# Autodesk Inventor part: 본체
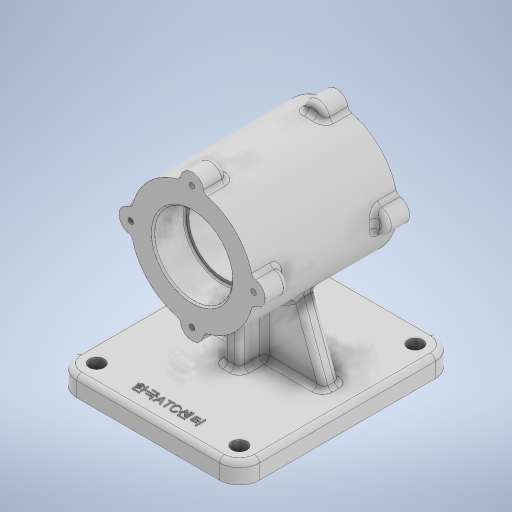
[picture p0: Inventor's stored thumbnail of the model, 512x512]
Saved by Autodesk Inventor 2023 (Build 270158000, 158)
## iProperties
Created: 2023-08
Part Number: 본체
Material: 일반
Document SubType Name: Modeling
Designer: asung
Density: 1 g/cm^3
Appearance: 기본값
Author: asung
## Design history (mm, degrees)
sketch "스케치1"
  geometry: L1 (43, 65)-(-43, 65); L2 (-55, 53)-(-55, -53); L3 (-43, -65)-(43, -65); L4 (55, -53)-(55, 53); L5 (55, 65)-(-55, -65); L6 (-55, 65)-(55, -65); C1 r 4.5 at (43, 53); C2 r 4.5 at (43, -53); C3 r 4.5 at (-43, 53); C4 r 4.5 at (-43, -53); A1 r 12 centre (-43, 53) between (-43, 65) and (-55, 53); A2 r 12 centre (-43, -53) between (-55, -53) and (-43, -65); A3 r 12 centre (43, -53) between (43, -65) and (55, -53); A4 r 12 centre (43, 53) between (55, 53) and (43, 65); 1 further point
  constraints: 12 end point, 8 centre point, 8 point on circle, 8 point on line, 8 tangent, 4 coincident, 3 equal radius, 2 midpoint, 2 parallel, 1 horizontal, 1 perpendicular
  dimensions: "d0" = 110 distance of L6.end L5.end; "d1" = 130 distance of L5.end L6.start; "d2" = 12 radius of A1; "d3" = 9 diameter of C1; "d4" = 9 diameter of C2; "d5" = 9 diameter of C3; "d6" = 9 diameter of C4
extrude "돌출1" new body sketch "스케치1" distance "d7" = 12; taper "d8" = 0 deg
fillet "모깎기1" dims "d9" = 3
sketch "스케치2"
  geometry: L1 (12, 62)-(12, -62) reference; L2 (9, -65)-(0, -65) reference; L3 (0, -65)-(0, 65) reference; L4 (0, 65)-(9, 65) reference; L5 (0, 53)-(0, 65) reference; L6 (0, 65)-(0, -5); L7 (0, -53)-(0, 53) reference; L8 (0, 65)-(0, -5); L9 (0, -5)-(82, -5); L10 (82, 38.5)-(82, -48.5); L11 (82, 38.5)-(119, 38.5); L12 (119, 38.5)-(119, -48.5); L13 (119, -48.5)-(82, -48.5); A1 r 3 centre (9, 62) between (12, 62) and (9, 65) reference; A2 r 3 centre (9, -62) between (9, -65) and (12, -62) reference; 1 further point
  constraints: 14 end point, 2 perpendicular, 2 vertical, 1 horizontal, 1 midpoint, 1 point on line
  dimensions: "d12" = 70 distance of L3.end L6.end; "d13" = 82 distance of L9.end L6.end; "d14" = 87 distance of L10.start L10.end; "d15" = 37 distance of L10.start L11.end; "d16" = 87 distance of L11.end L12.end
  node "절단 모서리 투영1"
sketch "스케치3"
  geometry: 1 further point
sketch "스케치4"
  geometry: 1 further point
revolve "회전1" stored, may be unused: angle "d17" = 90 deg
sketch "스케치5"
  geometry: C1 r 37 at (0, 0) reference; 2 further points
  constraints: 1 coincident
hole "구멍1" sketch "스케치5" at (0, 0) diameter "d18" = 42; stored, may be unused: countersink angle "d22" = 90 deg, drill point angle "d24" = 0 deg; dims "d19" = 10, "d20" = 47, "d21" = 19, "d23" = 87
sketch "스케치6"
  geometry: C1 r 37 at (0, 0) reference; 2 further points
  constraints: 1 coincident
hole "구멍2" sketch "스케치6" at (0, 0) diameter "d25" = 42; stored, may be unused: countersink angle "d29" = 90 deg, drill point angle "d31" = 0 deg; dims "d26" = 6, "d27" = 47, "d28" = 19, "d30" = 87
chamfer "모따기1" distance "d32" = 1; stored, may be unused: second distance "d33" = 2, angle "d34" = 45 deg
fillet "모깎기2" dims "d35" = 1
sketch "스케치7"
  geometry: 1 further point
sketch "스케치8"
  geometry: C1 r 37 at (0, 0) reference; C2 r 24.5 at (0, 0) reference; C3 r 7 at (0, 37); 2 further points
  constraints: 1 centre point, 1 vertical alignment, 1 other
  dimensions: "d36" = 14 diameter of C3
extrude "돌출2" join sketch "스케치8" distance "d37" = 14; taper "d38" = 0 deg
fillet "모깎기3" dims "d39" = 3
sketch "스케치9"
  geometry: C1 r 24.5 at (0, 0) reference; C2 r 7 at (0, 37); A1 r 37 centre (0, 0) between (-3.994, 36.784) and (3.994, 36.784) reference; A2 r 4 centre (0, 37) between (3.994, 36.784) and (-3.994, 36.784) reference; 1 further point
  constraints: 1 centre point, 1 coincident
  dimensions: "d43" = 14 diameter of C2
extrude "돌출3" join sketch "스케치9" distance "d44" = 14; taper "d45" = 0 deg
fillet "모깎기4" dims "d46" = 3
sketch "스케치10"
  geometry: A1 r 7 centre (0, 0) between (6.969, -0.662) and (-6.969, -0.662) reference; 2 further points
  constraints: 1 coincident
hole "구멍3" sketch "스케치10" at (0, 0) diameter "d50" = 3.242; stored, may be unused: countersink angle "d54" = 90 deg, drill point angle "d56" = 118 deg; dims "d51" = 8, "d52" = 47, "d53" = 19, "d55" = 10
sketch "스케치11"
  geometry: A1 r 7 centre (0, 0) between (6.969, -0.662) and (-6.969, -0.662) reference; 2 further points
  constraints: 1 coincident
hole "구멍4" sketch "스케치11" at (0, 0) diameter "d60" = 3.242; stored, may be unused: countersink angle "d64" = 90 deg, drill point angle "d66" = 118 deg; dims "d61" = 8, "d62" = 4, "d63" = 2, "d65" = 10
sketch "스케치12"
  geometry: L1 (52, -53)-(52, 53) reference; L2 (43, 62)-(-43, 62) reference; L3 (-52, 53)-(-52, -53) reference; L4 (-43, -62)-(43, -62) reference; L5 (-43, -65)-(43, -65) reference; L6 (-55, 53)-(-55, -53) reference; L7 (55, -53)-(55, 53) reference; L8 (-5, 25)-(-5, -15); L9 (5, 25)-(5, -15); L10 (-55, -15)-(-52, -15); L11 (-55, 5)-(-52, 5); L12 (-55, 25)-(-52, 25); L13 (-5, 25)-(5, 25); L14 (52, 25)-(55, 25); L15 (52, 5)-(55, 5); L16 (-5, -15)-(5, -15); L17 (52, -15)-(55, -15); C1 r 4.5 at (-43, -53) reference; C2 r 4.5 at (-43, 53) reference; C3 r 4.5 at (43, -53) reference; C4 r 4.5 at (43, 53) reference; A1 r 9 centre (43, -53) between (43, -62) and (52, -53) reference; A2 r 9 centre (43, 53) between (52, 53) and (43, 62) reference; A3 r 9 centre (-43, 53) between (-43, 62) and (-52, 53) reference; A4 r 9 centre (-43, -53) between (-52, -53) and (-43, -62) reference
  constraints: 20 end point, 14 parallel, 8 point on line
  node "절단 모서리 투영2"
sketch "스케치13"
  geometry: 1 further point
node "작업 평면2"
sketch "스케치14"
  geometry: L1 (-9, 12)-(95, 12) reference; L2 (98, 9)-(98, 0) reference; L3 (98, 0)-(-12, 0) reference; L4 (-12, 0)-(-12, 9) reference; L5 (2, 12)-(19.068, 58.893); L6 (84, 12)-(67.201, 58.155); C1 r 37 at (43, 82) reference; C2 r 21 at (43, 82) reference; A1 r 3 centre (-9, 9) between (-9, 12) and (-12, 9) reference; A2 r 3 centre (95, 9) between (98, 9) and (95, 12) reference; 2 further points
  constraints: 4 end point, 1 midpoint, 1 point on line
  dimensions: "d78" = 14 distance from line of L4 L5.start; "d79" = 14 horizontal distance of point (98, 4.5) L6.start; "d80" = 110 deg angle of L1 L5
  node "절단 모서리 투영3"
sketch "스케치15"
  geometry: L1 (0, -64.567)-(0, 5.433); L2 (0, 5.433)-(-55, 5.433); L3 (-55, 53)-(-55, -53) reference; L4 (0, 5.433)-(55, 5.433); L5 (55, -53)-(55, 53) reference; 1 further point
  constraints: 6 end point, 3 point on line, 1 horizontal, 1 vertical
  dimensions: "d96" = 70 distance of L1.start L1.end
extrude "돌출5" join sketch "스케치12" stored distance "d106" = 10; taper "d107" = 0 deg
feature "리브3" dims "d108" = 1, "d109" = 10, "d110" = 0, "d111" = 0, "d112" = 1, "d113" = 1
feature "리브4" dims "d114" = 1, "d115" = 10, "d116" = 0, "d117" = 0, "d118" = 1, "d119" = 1
fillet "모깎기7" dims "d120" = 3
fillet "모깎기8" dims "d121" = 3
sketch "스케치16"
  geometry: L1 (-43, -65)-(43, -65) reference; L2 (43, 65)-(-43, 65) reference; L3 (0, -65)-(0, 5); 2 further points
  constraints: 2 end point, 1 midpoint, 1 vertical, 1 other
  dimensions: "d124" = 70 distance of L3.start L3.end; "d125" = 58 vertical distance of point (0.301, -53) L3.end
feature "엠보싱1" sketch "스케치16" dims "d126" = 0.5, "d127" = 0
fillet "모깎기9" dims "d128" = 3
feature "Ҡ耀Ң耀Ҥ耀Ҧ耀Ҩ耀Ҫ耀Ҭ耀Ү耀" dims "d0" = 110, "d1" = 130, "d2" = 12, "d3" = 9, "d4" = 9, "d5" = 9, "d6" = 9, "d7" = 12, "d8" = 0, "d9" = 3, "d12" = 70, "d13" = 82, "d14" = 87, "d15" = 37, "d16" = 87, "d17" = 90 deg, "d18" = 42, "d19" = 10, "d20" = 47, "d21" = 19, "d22" = 90 deg, "d23" = 87, "d24" = 0, "d25" = 42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
node "솔리드1"
pattern_circular "원형 패턴1" dims angle "d41" = 360 deg
pattern_circular "원형 패턴2" dims angle "d48" = 360 deg
pattern_circular "원형 패턴3" dims angle "d58" = 360 deg
pattern_circular "원형 패턴4" dims angle "d68" = 360 deg
node "투영된 루프1"
node "투영된 루프2"
feature "A9D066F2-1C7D-4E18-AEED-F7BC21143FA4" dims "d18" = 42, "d19" = 10, "d20" = 47, "d21" = 19, "d22" = 90 deg, "d23" = 87, "d24" = 0
